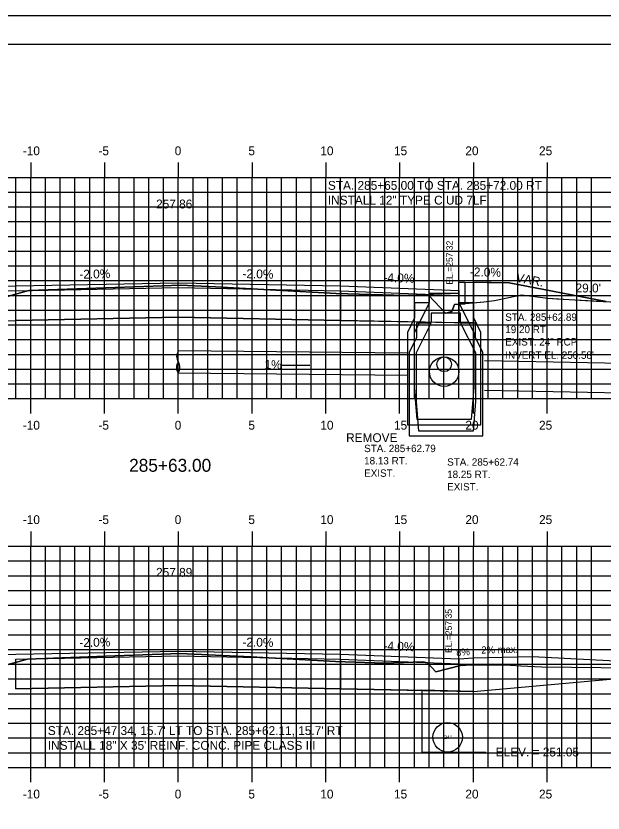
# Model space of a CAD drawing. Extents: x 856680 to 856850, y 366268 to 366378.
# Drawn here: x 856752.1 to 856791.9, y 366324.1 to 366378.2 of the extents above; entities that cross this region are included whole.
import ezdxf

# ---------------------------------------------------------------- set-up
doc = ezdxf.new("R2010")
doc.units = 0
for name, color, linetype in [('ANNOTATION', 7, 'Continuous'), ('BORDER', 7, 'Continuous'), ('D_Curb_Type_1_Rt', 7, 'Continuous'), ('D_Drainage_CB_TypeA1-B1', 7, 'Continuous'), ('D_Drainage_Culvert', 7, 'Continuous'), ('D_Drainage_Text', 7, 'Continuous'), ('D_Roadway_Centerline', 7, 'Continuous'), ('D_Roadway_Centerline_Text', 7, 'Continuous'), ('D_Roadway_Drive_Gravel_RT', 7, 'Continuous'), ('D_Roadway_Drive_SubGrade', 7, 'Continuous'), ('D_Roadway_Edge_Shoulder', 7, 'Continuous'), ('D_Roadway_FinishedGrade', 7, 'Continuous'), ('D_Roadway_SubGrade', 7, 'Continuous'), ('D_Text_Monospaced', 7, 'Continuous'), ('D_Text_Standard', 7, 'Continuous'), ('H_V ANNOTATION', 7, 'Continuous'), ('JUNK COM EXC', 7, 'Continuous'), ('JUNK FILL', 7, 'Continuous'), ('junk strct exc', 7, 'Continuous'), ('MAJOR', 7, 'Continuous'), ('MINOR', 7, 'Continuous'), ('PDRAIN', 7, 'Continuous'), ('PLOT BOUNDARY', 7, 'Continuous'), ('S_Drainage_CB', 7, 'Continuous'), ('S_Drainage_Culvert_Top', 7, 'Continuous'), ('S_Roadway_Centerline', 7, 'Continuous')]:
    doc.layers.add(name, color=color, linetype=linetype)

msp = doc.modelspace()

# ---------------------------------------------------------------- linework, layer by layer
at = {"layer": 'ANNOTATION'}
msp.add_line((856770.132, 366354.511), (856772.031, 366354.511), dxfattribs=at)
at = {"layer": 'BORDER'}
msp.add_line((856848.116, 366376.236), (856688.116, 366376.236), dxfattribs=at)
at = {"layer": 'D_Curb_Type_1_Rt'}
msp.add_lwpolyline([(856782.533, 366360.142), (856782.533, 366358.642), (856782.116, 366358.642), (856782.116, 366360.142)], close=True, dxfattribs=at)
at = {"layer": 'D_Drainage_CB_TypeA1-B1'}
for p, q in [((856779.131, 366358.721), (856779.131, 366357.704)), ((856779.131, 366356.72), (856780.148, 366358.721)), ((856780.148, 366358.721), (856779.131, 366358.721)), ((856783.134, 366358.721), (856782.117, 366358.721)), ((856782.117, 366358.721), (856783.134, 366356.72)), ((856783.134, 366357.704), (856783.134, 366358.721)), ((856779.131, 366357.704), (856778.639, 366356.72)), ((856783.626, 366356.72), (856783.134, 366357.704)), ((856778.639, 366356.72), (856778.639, 366350.457)), ((856779.131, 366352.988), (856779.131, 366356.72)), ((856783.134, 366356.72), (856783.134, 366352.988)), ((856783.626, 366350.457), (856783.626, 366356.72)), ((856779.295, 366350.818), (856779.131, 366352.988)), ((856783.134, 366352.988), (856782.97, 366350.818)), ((856778.639, 366350.457), (856783.626, 366350.457)), ((856782.97, 366350.818), (856779.295, 366350.818))]:
    msp.add_line(p, q, dxfattribs=at)
msp.add_lwpolyline([(856779.623, 366358.763), (856780.148, 366358.763), (856780.148, 366359.386), (856782.117, 366359.386), (856782.117, 366358.763), (856782.642, 366358.763)], dxfattribs=at)
at = {"layer": 'D_Drainage_Culvert'}
for p, q in [((856778.654, 366355.316), (856763.131, 366355.472)), ((856778.639, 366353.816), (856763.116, 366353.972))]:
    msp.add_line(p, q, dxfattribs=at)
for centre, radius, start, end in [((856763.627, 366355.092), 0.625, 142.5572, 216.297), ((856763.62, 366354.342), 0.625, 142.5572, 216.297), ((856762.478, 366354.353), 0.744, 329.1462, 29.708)]:
    msp.add_arc(centre, radius, start, end, dxfattribs=at)
at = {"layer": 'D_Roadway_Centerline'}
msp.add_lwpolyline([(856752.116, 366334.911), (856763.116, 366335.131), (856774.116, 366334.911)], dxfattribs=at)
at = {"layer": 'D_Roadway_Drive_Gravel_RT'}
for p, q in [((856783.117, 366334.671), (856787.117, 366334.751)), ((856787.117, 366334.751), (856804.736, 366333.87)), ((856782.117, 366334.591), (856783.117, 366334.671))]:
    msp.add_line(p, q, dxfattribs=at)
at = {"layer": 'D_Roadway_Drive_SubGrade'}
for p, q in [((856783.116, 366332.397), (856793.116, 366333.283)), ((856782.116, 366332.417), (856783.116, 366332.397))]:
    msp.add_line(p, q, dxfattribs=at)
at = {"layer": 'D_Roadway_Edge_Shoulder'}
for p, q in [((856782.117, 366359.558), (856782.116, 366359.225)), ((856782.117, 366334.591), (856782.116, 366334.257))]:
    msp.add_line(p, q, dxfattribs=at)
for points in [[(856744.116, 366359.558), (856752.116, 366359.878), (856763.116, 366360.098), (856774.116, 366359.878), (856782.117, 366359.558)], [(856744.116, 366334.591), (856752.116, 366334.911), (856763.116, 366335.131), (856774.116, 366334.911), (856782.117, 366334.591)]]:
    msp.add_lwpolyline(points, dxfattribs=at)
at = {"layer": 'D_Roadway_FinishedGrade'}
for points in [[(856782.533, 366360.141), (856785.533, 366360.081)], [(856785.533, 366360.081), (856792.116, 366358.816)]]:
    msp.add_lwpolyline(points, dxfattribs=at)
at = {"layer": 'D_Roadway_SubGrade'}
msp.add_lwpolyline([(856783.116, 366360.13), (856783.116, 366357.365), (856782.116, 366357.385)], dxfattribs=at)
for points in [[(856752.116, 366357.545), (856752.116, 366359.545), (856763.116, 366359.765), (856774.116, 366359.545), (856774.116, 366357.545), (856763.116, 366357.765)], [(856752.116, 366359.545), (856744.116, 366359.225), (856744.116, 366357.385), (856752.116, 366357.545)], [(856774.116, 366359.545), (856782.116, 366359.225), (856782.116, 366357.385), (856774.116, 366357.545)], [(856752.116, 366332.577), (856752.116, 366334.577), (856763.116, 366334.797), (856774.116, 366334.577), (856774.116, 366332.577), (856763.116, 366332.797)], [(856774.116, 366334.577), (856782.116, 366334.257), (856782.116, 366332.417), (856774.116, 366332.577)]]:
    msp.add_lwpolyline(points, close=True, dxfattribs=at)
at = {"layer": 'D_Text_Standard'}
msp.add_lwpolyline([(856783.116, 366328.286), (856783.267, 366328.286), (856783.947, 366328.286)], dxfattribs=at)
at = {"layer": 'JUNK COM EXC'}
for points in [[(856743.116, 366357.365), (856752.116, 366357.545), (856763.116, 366357.765), (856774.116, 366357.545), (856783.116, 366357.365), (856783.116, 366358.735), (856781.829, 366358.609), (856781.645, 366358.139), (856781.237, 366358.041), (856781.231, 366358.037), (856780.097, 366359.226), (856779.932, 366359.263), (856778.509, 366359.225), (856773.825, 366359.36), (856765.638, 366359.82), (856763.273, 366359.928), (856760.779, 366359.841), (856752.995, 366359.558), (856751.037, 366359.015)], [(856752.116, 366332.577), (856763.116, 366332.797), (856774.116, 366332.577), (856783.116, 366332.397), (856783.117, 366334.191), (856782.982, 366334.189), (856782.24, 366334.148), (856780.564, 366333.721), (856779.994, 366334.319), (856779.689, 366334.387), (856777.064, 366334.317), (856773.78, 366334.412), (856768.041, 366334.734), (856763.246, 366334.954), (856758.19, 366334.778), (856752.903, 366334.586), (856749.011, 366333.506)]]:
    msp.add_lwpolyline(points, dxfattribs=at)
at = {"layer": 'JUNK FILL'}
msp.add_lwpolyline([(856783.116, 366360.13), (856783.116, 366358.735), (856783.824, 366358.804), (856784.545, 366358.884), (856786.381, 366359.268), (856788.154, 366359.038), (856788.771, 366359.002), (856792.116, 366358.816), (856785.533, 366360.081)], close=True, dxfattribs=at)
at = {"layer": 'junk strct exc'}
msp.add_lwpolyline([(856779.616, 366332.467), (856779.616, 366328.286), (856783.116, 366328.286), (856783.116, 366332.397)], close=True, dxfattribs=at)
at = {"layer": 'MAJOR'}
for p, q in [((856753.116, 366368.238), (856753.116, 366367.236)), ((856758.116, 366368.238), (856758.116, 366367.236)), ((856763.116, 366368.238), (856763.116, 366367.236)), ((856768.116, 366368.238), (856768.116, 366367.236)), ((856773.116, 366368.238), (856773.116, 366367.236)), ((856778.116, 366368.238), (856778.116, 366367.236)), ((856783.116, 366368.238), (856783.116, 366367.236)), ((856788.116, 366368.238), (856788.116, 366367.236)), ((856693.116, 366367.236), (856833.116, 366367.236)), ((856693.116, 366367.236), (856833.116, 366367.236)), ((856753.116, 366352.236), (856753.116, 366367.236)), ((856758.116, 366352.236), (856758.116, 366367.236)), ((856763.116, 366352.236), (856763.116, 366367.236)), ((856768.116, 366352.236), (856768.116, 366367.236)), ((856773.116, 366352.236), (856773.116, 366367.236)), ((856778.116, 366352.236), (856778.116, 366367.236)), ((856783.116, 366352.236), (856783.116, 366367.236)), ((856788.116, 366352.236), (856788.116, 366367.236)), ((856693.116, 366362.236), (856833.116, 366362.236)), ((856693.116, 366357.236), (856833.116, 366357.236)), ((856693.116, 366352.236), (856833.116, 366352.236)), ((856693.116, 366352.236), (856833.116, 366352.236)), ((856753.116, 366351.234), (856753.116, 366352.236)), ((856758.116, 366351.234), (856758.116, 366352.236)), ((856763.116, 366351.234), (856763.116, 366352.236)), ((856768.116, 366351.234), (856768.116, 366352.236)), ((856773.116, 366351.234), (856773.116, 366352.236)), ((856778.116, 366351.234), (856778.116, 366352.236)), ((856783.116, 366351.234), (856783.116, 366352.236)), ((856788.116, 366351.234), (856788.116, 366352.236)), ((856753.116, 366343.238), (856753.116, 366342.236)), ((856758.116, 366343.238), (856758.116, 366342.236)), ((856763.116, 366343.238), (856763.116, 366342.236)), ((856768.116, 366343.238), (856768.116, 366342.236)), ((856773.116, 366343.238), (856773.116, 366342.236)), ((856778.116, 366343.238), (856778.116, 366342.236)), ((856783.116, 366343.238), (856783.116, 366342.236)), ((856788.116, 366343.238), (856788.116, 366342.236)), ((856693.116, 366342.236), (856833.116, 366342.236)), ((856693.116, 366342.236), (856833.116, 366342.236)), ((856753.116, 366327.236), (856753.116, 366342.236)), ((856758.116, 366327.236), (856758.116, 366342.236)), ((856763.116, 366327.236), (856763.116, 366342.236)), ((856768.116, 366327.236), (856768.116, 366342.236)), ((856773.116, 366327.236), (856773.116, 366342.236)), ((856778.116, 366327.236), (856778.116, 366342.236)), ((856783.116, 366327.236), (856783.116, 366342.236)), ((856788.116, 366327.236), (856788.116, 366342.236)), ((856693.116, 366337.236), (856833.116, 366337.236)), ((856693.116, 366332.236), (856833.116, 366332.236)), ((856693.116, 366327.236), (856833.116, 366327.236)), ((856693.116, 366327.236), (856833.116, 366327.236)), ((856753.116, 366326.234), (856753.116, 366327.236)), ((856758.116, 366326.234), (856758.116, 366327.236)), ((856763.116, 366326.234), (856763.116, 366327.236)), ((856768.116, 366326.234), (856768.116, 366327.236)), ((856773.116, 366326.234), (856773.116, 366327.236)), ((856778.116, 366326.234), (856778.116, 366327.236)), ((856783.116, 366326.234), (856783.116, 366327.236)), ((856788.116, 366326.234), (856788.116, 366327.236))]:
    msp.add_line(p, q, dxfattribs=at)
at = {"layer": 'MINOR'}
for p, q in [((856752.116, 366352.236), (856752.116, 366367.236)), ((856754.116, 366352.236), (856754.116, 366367.236)), ((856755.116, 366352.236), (856755.116, 366367.236)), ((856756.116, 366352.236), (856756.116, 366367.236)), ((856757.116, 366352.236), (856757.116, 366367.236)), ((856759.116, 366352.236), (856759.116, 366367.236)), ((856760.116, 366352.236), (856760.116, 366367.236)), ((856761.116, 366352.236), (856761.116, 366367.236)), ((856762.116, 366352.236), (856762.116, 366367.236)), ((856764.116, 366352.236), (856764.116, 366367.236)), ((856765.116, 366352.236), (856765.116, 366367.236)), ((856766.116, 366352.236), (856766.116, 366367.236)), ((856767.116, 366352.236), (856767.116, 366367.236)), ((856769.116, 366352.236), (856769.116, 366367.236)), ((856770.116, 366352.236), (856770.116, 366367.236)), ((856771.116, 366352.236), (856771.116, 366367.236)), ((856772.116, 366352.236), (856772.116, 366367.236)), ((856774.116, 366352.236), (856774.116, 366367.236)), ((856775.116, 366352.236), (856775.116, 366367.236)), ((856776.116, 366352.236), (856776.116, 366367.236)), ((856777.116, 366352.236), (856777.116, 366367.236)), ((856779.116, 366352.236), (856779.116, 366367.236)), ((856780.116, 366352.236), (856780.116, 366367.236)), ((856781.116, 366352.236), (856781.116, 366367.236)), ((856782.116, 366352.236), (856782.116, 366367.236)), ((856784.116, 366352.236), (856784.116, 366367.236)), ((856785.116, 366352.236), (856785.116, 366367.236)), ((856786.116, 366352.236), (856786.116, 366367.236)), ((856787.116, 366352.236), (856787.116, 366367.236)), ((856789.116, 366352.236), (856789.116, 366367.236)), ((856790.116, 366352.236), (856790.116, 366367.236)), ((856791.116, 366352.236), (856791.116, 366367.236)), ((856693.116, 366366.236), (856833.116, 366366.236)), ((856693.116, 366365.236), (856833.116, 366365.236)), ((856693.116, 366364.236), (856833.116, 366364.236)), ((856693.116, 366363.236), (856833.116, 366363.236)), ((856693.116, 366361.236), (856833.116, 366361.236)), ((856693.116, 366360.236), (856833.116, 366360.236)), ((856693.116, 366359.236), (856833.116, 366359.236)), ((856693.116, 366358.236), (856833.116, 366358.236)), ((856693.116, 366356.236), (856833.116, 366356.236)), ((856693.116, 366355.236), (856833.116, 366355.236)), ((856693.116, 366354.236), (856833.116, 366354.236)), ((856693.116, 366353.236), (856833.116, 366353.236)), ((856754.116, 366327.236), (856754.116, 366342.236)), ((856755.116, 366327.236), (856755.116, 366342.236)), ((856756.116, 366327.236), (856756.116, 366342.236)), ((856757.116, 366327.236), (856757.116, 366342.236)), ((856759.116, 366327.236), (856759.116, 366342.236)), ((856760.116, 366327.236), (856760.116, 366342.236)), ((856761.116, 366327.236), (856761.116, 366342.236)), ((856762.116, 366327.236), (856762.116, 366342.236)), ((856764.116, 366327.236), (856764.116, 366342.236)), ((856765.116, 366327.236), (856765.116, 366342.236)), ((856766.116, 366327.236), (856766.116, 366342.236)), ((856767.116, 366327.236), (856767.116, 366342.236)), ((856769.116, 366327.236), (856769.116, 366342.236)), ((856770.116, 366327.236), (856770.116, 366342.236)), ((856771.116, 366327.236), (856771.116, 366342.236)), ((856772.116, 366327.236), (856772.116, 366342.236)), ((856774.116, 366327.236), (856774.116, 366342.236)), ((856775.116, 366327.236), (856775.116, 366342.236)), ((856776.116, 366327.236), (856776.116, 366342.236)), ((856777.116, 366327.236), (856777.116, 366342.236)), ((856779.116, 366327.236), (856779.116, 366342.236)), ((856780.116, 366327.236), (856780.116, 366342.236)), ((856781.116, 366327.236), (856781.116, 366342.236)), ((856782.116, 366327.236), (856782.116, 366342.236)), ((856784.116, 366327.236), (856784.116, 366342.236)), ((856785.116, 366327.236), (856785.116, 366342.236)), ((856786.116, 366327.236), (856786.116, 366342.236)), ((856787.116, 366327.236), (856787.116, 366342.236)), ((856789.116, 366327.236), (856789.116, 366342.236)), ((856790.116, 366327.236), (856790.116, 366342.236)), ((856791.116, 366327.236), (856791.116, 366342.236)), ((856693.116, 366341.236), (856833.116, 366341.236)), ((856693.116, 366340.236), (856833.116, 366340.236)), ((856693.116, 366339.236), (856833.116, 366339.236)), ((856693.116, 366338.236), (856833.116, 366338.236)), ((856693.116, 366336.236), (856833.116, 366336.236)), ((856693.116, 366335.236), (856833.116, 366335.236)), ((856693.116, 366334.236), (856833.116, 366334.236)), ((856693.116, 366333.236), (856833.116, 366333.236)), ((856693.116, 366331.236), (856833.116, 366331.236)), ((856693.116, 366330.236), (856833.116, 366330.236)), ((856693.116, 366329.236), (856833.116, 366329.236)), ((856693.116, 366328.236), (856833.116, 366328.236))]:
    msp.add_line(p, q, dxfattribs=at)
at = {"layer": 'PDRAIN'}
msp.add_lwpolyline([(856779.616, 366332.467), (856779.616, 366328.286), (856783.116, 366328.286), (856783.116, 366332.397)], dxfattribs=at)
for centre, radius in [((856781.133, 366354.066), 1), ((856781.133, 366354.566), 0.5), ((856781.366, 366329.286), 1)]:
    msp.add_circle(centre, radius, dxfattribs=at)
at = {"layer": 'PLOT BOUNDARY'}
msp.add_lwpolyline([(856680.023, 366268.177), (856850.023, 366268.177), (856850.023, 366378.177), (856680.023, 366378.177)], close=True, dxfattribs=at)
at = {"layer": 'S_Drainage_CB'}
for p, q in [((856780.244, 366357.358), (856779.26, 366357.358)), ((856779.26, 366357.358), (856779.26, 366356.373)), ((856779.26, 366355.356), (856780.244, 366357.358)), ((856783.262, 366357.358), (856782.245, 366357.358)), ((856782.245, 366357.358), (856783.262, 366355.356)), ((856783.262, 366356.373), (856783.262, 366357.358)), ((856779.26, 366356.373), (856778.768, 366355.356)), ((856783.754, 366355.356), (856783.262, 366356.373)), ((856778.768, 366355.356), (856778.768, 366349.713)), ((856779.26, 366352.043), (856779.26, 366355.356)), ((856783.262, 366355.356), (856783.262, 366352.043)), ((856783.754, 366349.713), (856783.754, 366355.356)), ((856779.424, 366350.041), (856779.26, 366352.043)), ((856783.262, 366352.043), (856783.098, 366350.041)), ((856783.098, 366350.041), (856779.424, 366350.041)), ((856778.768, 366349.713), (856783.754, 366349.713))]:
    msp.add_line(p, q, dxfattribs=at)
msp.add_lwpolyline([(856782.737, 366357.399), (856782.245, 366357.399), (856782.245, 366358.023), (856780.244, 366358.023), (856780.244, 366357.399), (856779.752, 366357.399)], dxfattribs=at)
at = {"layer": 'S_Drainage_Culvert_Top'}
for p, q in [((856783.873, 366354.819), (856820.78, 366354.081)), ((856783.873, 366352.818), (856820.74, 366352.081))]:
    msp.add_line(p, q, dxfattribs=at)
at = {"layer": 'S_Roadway_Centerline'}
for points in [[(856751.037, 366359.015), (856752.995, 366359.558), (856760.779, 366359.841), (856763.273, 366359.928), (856765.638, 366359.82), (856773.825, 366359.36), (856778.509, 366359.225), (856779.932, 366359.263), (856780.097, 366359.226), (856781.231, 366358.037), (856781.237, 366358.041), (856781.645, 366358.139), (856781.829, 366358.609), (856783.824, 366358.804), (856784.545, 366358.884), (856786.381, 366359.268), (856788.154, 366359.038), (856791.431, 366358.849), (856806.317, 366358.133)], [(856749.011, 366333.506), (856752.903, 366334.586), (856758.19, 366334.778), (856763.246, 366334.954), (856768.041, 366334.734), (856773.78, 366334.412), (856777.064, 366334.317), (856779.689, 366334.387), (856779.994, 366334.319), (856780.564, 366333.721), (856782.24, 366334.148), (856782.982, 366334.189), (856783.634, 366334.2), (856784.005, 366334.201), (856784.614, 366334.195), (856785.623, 366334.166), (856786.336, 366334.131), (856787.76, 366334.057), (856807.868, 366333.829)]]:
    msp.add_lwpolyline(points, dxfattribs=at)

# ---------------------------------------------------------------- texts
at = {"layer": 'ANNOTATION'}
for s, rotation, p in [('-2.0%', 1.1458, (856756.419, 366360.365)), ('-2.0%', 358.8542, (856767.459, 366360.412)), ('-4.0%', 357.7094, (856777.011, 366360.163)), ('-2.0%', 358.8543, (856782.876, 366360.535)), ('1%', 359.4271, (856768.959, 366354.251)), ('-2.0%', 1.1458, (856756.419, 366335.397)), ('-2.0%', 358.8542, (856767.459, 366335.444)), ('-4.0%', 357.7094, (856777.01, 366335.196))]:
    msp.add_text(s, height=0.6, rotation=rotation, dxfattribs=at).set_placement(p)
at = {"layer": 'D_Drainage_Text'}
for s, p in [('STA. 285+65.00 TO STA. 285+72.00 RT', (856773.255, 366366.392)), ('INSTALL 12" TYPE C UD 7LF', (856773.255, 366365.392)), ("STA. 285+47.34, 15.7' LT TO STA. 285+62.11, 15.7' RT", (856754.276, 366329.436)), ('INSTALL 18" X 35\' REINF. CONC. PIPE CLASS III', (856754.276, 366328.436))]:
    msp.add_text(s, height=0.6, dxfattribs=at).set_placement(p)
at = {"layer": 'D_Roadway_Centerline_Text'}
for s, p in [('257.86', (856761.612, 366365.13)), ('257.89', (856761.612, 366340.163))]:
    msp.add_text(s, height=0.6, dxfattribs=at).set_placement(p)
at = {"layer": 'D_Roadway_Drive_Gravel_RT'}
for s, rotation, p in [('8%', 4.5739, (856781.964, 366334.784)), ('2% max.', 1.1922, (856783.654, 366334.958))]:
    msp.add_text(s, height=0.48, rotation=rotation, dxfattribs=at).set_placement(p)
at = {"layer": 'D_Text_Monospaced'}
for s, height, p in [('STA. 285+62.89', 0.49998, (856785.275, 366357.512)), ('19.20 RT.', 0.5, (856785.275, 366356.678)), ('EXIST. 24" RCP', 0.49998, (856785.275, 366355.838)), ("INVERT EL. 250.58'", 0.49998, (856785.275, 366354.936)), ('STA. 285+62.79', 0.49998, (856775.711, 366348.613)), ('18.13 RT.', 0.5, (856775.711, 366347.779)), ('STA. 285+62.74', 0.49998, (856781.336, 366347.691)), ('EXIST. ', 0.5, (856775.711, 366346.939)), ('18.25 RT.', 0.5, (856781.336, 366346.857)), ('EXIST. ', 0.5, (856781.336, 366346.017))]:
    msp.add_text(s, height=height, dxfattribs=at).set_placement(p)
at = {"layer": 'D_Text_Standard'}
for s, height, rotation, p in [(' EL.=257.32', 0.4335, 90, (856781.714, 366359.803)), ('VAR.', 0.6, 349.3141, (856785.972, 366360.169)), (' EL.=257.35', 0.4335, 90, (856781.651, 366334.836))]:
    msp.add_text(s, height=height, rotation=rotation, dxfattribs=at).set_placement(p)
for s, p in [("29.0'", (856790.038, 366359.436)), ('REMOVE', (856774.49, 366349.291)), ('ELEV. = 251.05', (856784.627, 366327.986))]:
    msp.add_text(s, height=0.6, dxfattribs=at).set_placement(p)
at = {"layer": 'H_V ANNOTATION'}
for s, height, p in [('-10', 0.6, (856752.581, 366368.736)), ('-5', 0.6, (856757.707, 366368.736)), ('0', 0.6, (856762.875, 366368.736)), ('5', 0.6, (856767.867, 366368.736)), ('10', 0.6, (856772.742, 366368.736)), ('15', 0.6, (856777.734, 366368.736)), ('20', 0.6, (856782.57, 366368.736)), ('25', 0.6, (856787.562, 366368.736)), ('-10', 0.6, (856752.581, 366350.136)), ('-5', 0.6, (856757.707, 366350.136)), ('0', 0.6, (856762.875, 366350.136)), ('5', 0.6, (856767.867, 366350.136)), ('10', 0.6, (856772.742, 366350.136)), ('15', 0.6, (856777.734, 366350.136)), ('20', 0.6, (856782.57, 366350.136)), ('25', 0.6, (856787.562, 366350.136)), ('285+63.00', 0.875, (856759.784, 366347.28)), ('-10', 0.6, (856752.581, 366343.736)), ('-5', 0.6, (856757.707, 366343.736)), ('0', 0.6, (856762.875, 366343.736)), ('5', 0.6, (856767.867, 366343.736)), ('10', 0.6, (856772.742, 366343.736)), ('15', 0.6, (856777.734, 366343.736)), ('20', 0.6, (856782.57, 366343.736)), ('25', 0.6, (856787.562, 366343.736)), ('-10', 0.6, (856752.581, 366325.136)), ('-5', 0.6, (856757.707, 366325.136)), ('0', 0.6, (856762.875, 366325.136)), ('5', 0.6, (856767.867, 366325.136)), ('10', 0.6, (856772.742, 366325.136)), ('15', 0.6, (856777.734, 366325.136)), ('20', 0.6, (856782.57, 366325.136)), ('25', 0.6, (856787.562, 366325.136))]:
    msp.add_text(s, height=height, dxfattribs=at).set_placement(p)
at = {"layer": 'PDRAIN'}
msp.add_text('24"', height=0.25, dxfattribs=at).set_placement((856781.124, 366329.161))
at = {"layer": 'S_Roadway_Centerline'}
for s, p in [('C', (856763.267, 366359.928)), ('L', (856763.273, 366359.921)), ('C', (856763.241, 366334.954)), ('L', (856763.246, 366334.947))]:
    msp.add_text(s, height=0.0146, dxfattribs=at).set_placement(p)

doc.saveas('drawing.dxf')
